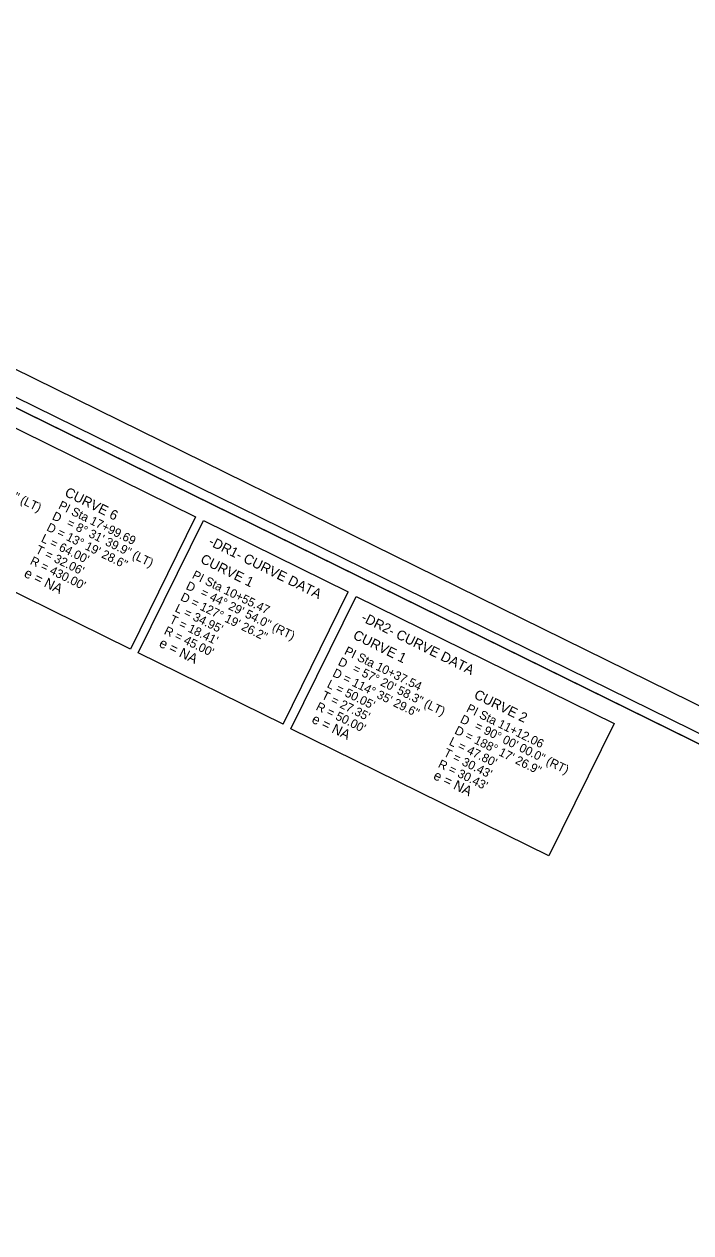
# Model space of a CAD drawing. Extents: x 1428420 to 1430540, y 857897 to 859622.
# Drawn here: x 1429472 to 1430006, y 858654 to 859622 of the extents above; entities that cross this region are included whole.
import ezdxf

# ---------------------------------------------------------------- set-up
doc = ezdxf.new("R2010")
doc.units = 0
for name, color, linetype in [('Prop Horizontal Alignment Curve and Spiral Data', 7, 'Continuous'), ('Sheet Plan CELL', 7, 'Continuous'), ('Sheet Plot Border Inside CELL', 7, 'Continuous'), ('Sheet Plot Border Outside CELL', 7, 'Continuous')]:
    doc.layers.add(name, color=color, linetype=linetype)

msp = doc.modelspace()

# ---------------------------------------------------------------- linework, layer by layer
at = {"layer": 'Prop Horizontal Alignment Curve and Spiral Data'}
for p, q in [((1429051.48, 859502.58), (1429609.77, 859227.87)), ((1429557.61, 859121.78), (1428999.32, 859396.49)), ((1429609.77, 859227.87), (1429557.61, 859121.78)), ((1429563.82, 859118.72), (1429615.98, 859224.82)), ((1429615.98, 859224.82), (1429731.93, 859167.76)), ((1429679.77, 859061.67), (1429731.93, 859167.76)), ((1429686.04, 859057.86), (1429738.2, 859163.96)), ((1429738.2, 859163.96), (1429944.85, 859062.27)), ((1429679.77, 859061.67), (1429563.82, 859118.72)), ((1429892.69, 858956.18), (1429686.04, 859057.86)), ((1429944.85, 859062.27), (1429892.69, 858956.18))]:
    msp.add_line(p, q, dxfattribs=at)
at = {"layer": 'Sheet Plan CELL'}
for points in [[(1430386.67, 858862), (1429040.75, 859524.27), (1428581.58, 858591.12), (1429927.48, 857928.86)], [(1428581.58, 858591.12), (1429040.71, 859524.26), (1430207.15, 858950.35), (1430140.91, 858815.69), (1430320.39, 858727.37), (1429927.48, 857928.86)]]:
    msp.add_lwpolyline(points, close=True, dxfattribs=at)
at = {"layer": 'Sheet Plot Border Inside CELL'}
msp.add_lwpolyline([(1428440.55, 858652.15), (1429935.37, 857916.62), (1430401.17, 858863.21), (1428906.33, 859598.76)], close=True, dxfattribs=at)
at = {"layer": 'Sheet Plot Border Outside CELL'}
msp.add_lwpolyline([(1428420.05, 858639.94), (1429930.59, 857896.67), (1430414.03, 858879.17), (1428903.5, 859622.44)], close=True, dxfattribs=at)

# ---------------------------------------------------------------- texts
at = {"layer": 'Prop Horizontal Alignment Curve and Spiral Data'}
for s, height, rotation, p in [('= 7%%d 19\' 32.1" (LT)', 7, 333.80952, (1429416.19, 859264.81)), ('CURVE 6', 7.875, 333.70139, (1429504.25, 859244.83)), ('PI Sta 17+99.69', 7, 333.80952, (1429499.27, 859234.74)), ('D', 7, 333.80952, (1429494.25, 859226.07)), ('D = 13%%d 19\' 28.6"', 7, 333.80952, (1429489.84, 859217.09)), ('= 8%%d 31\' 39.9" (LT)', 7, 333.80952, (1429505.91, 859220.66)), ("L = 64.00'", 7, 333.80952, (1429485.42, 859208.12)), ("T = 32.06'", 7, 333.80952, (1429481.01, 859199.15)), ('-DR1- CURVE DATA', 7.875, 333.70139, (1429619.52, 859205.54)), ("R = 430.00'", 7, 333.80952, (1429476.6, 859190.17)), ('CURVE 1', 7.875, 333.70139, (1429612.94, 859191.35)), ('e = NA', 7.875, 333.95463, (1429471.66, 859180.07)), ('PI Sta 10+55.47', 7, 334.09165, (1429606.36, 859178.9)), ('D', 7, 334.09165, (1429601.39, 859170.19)), ('D = 127%%d 19\' 26.2"', 7, 334.09165, (1429597.02, 859161.2)), ('= 44%%d 29\' 54.0" (RT)', 7, 334.09165, (1429613.07, 859164.85)), ("L = 34.95'", 7, 334.09165, (1429592.65, 859152.2)), ("T = 18.41'", 7, 334.09165, (1429588.28, 859143.21)), ('-DR2- CURVE DATA', 7.875, 333.70139, (1429741.74, 859144.68)), ("R = 45.00'", 7, 334.09165, (1429583.91, 859134.22)), ('CURVE 1', 7.875, 333.70139, (1429735.17, 859130.49)), ('e = NA', 7.875, 333.95463, (1429579.84, 859124.05)), ('PI Sta 10+37.54', 7, 333.76466, (1429728.27, 859118.04)), ('D', 7, 333.76466, (1429723.24, 859109.37)), ('D = 114%%d 35\' 29.6"', 7, 333.76466, (1429718.82, 859100.4)), ('= 57%%d 20\' 58.3" (LT)', 7, 333.76466, (1429734.9, 859103.95)), ("L = 50.05'", 7, 333.76466, (1429714.4, 859091.43)), ("T = 27.35'", 7, 333.76466, (1429709.98, 859082.46)), ('CURVE 2', 7.875, 333.70139, (1429832.07, 859082.8)), ("R = 50.00'", 7, 333.76466, (1429705.56, 859073.49)), ('PI Sta 11+12.06', 7, 333.76466, (1429825.99, 859072.03)), ('e = NA', 7.875, 333.95463, (1429702.06, 859063.19)), ('D', 7, 333.76466, (1429820.97, 859063.36)), ('D = 188%%d 17\' 26.9"', 7, 333.76466, (1429816.55, 859054.39)), ('= 90%%d 00\' 00.0" (RT)', 7, 333.76466, (1429832.63, 859057.94)), ("L = 47.80'", 7, 333.76466, (1429812.13, 859045.42)), ("T = 30.43'", 7, 333.76466, (1429807.71, 859036.45)), ("R = 30.43'", 7, 333.76466, (1429803.29, 859027.48)), ('e = NA', 7.875, 333.95463, (1429799.47, 859018.04))]:
    msp.add_text(s, height=height, rotation=rotation, dxfattribs=at).set_placement(p)

doc.saveas('drawing.dxf')
